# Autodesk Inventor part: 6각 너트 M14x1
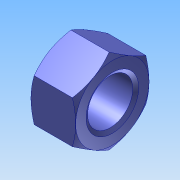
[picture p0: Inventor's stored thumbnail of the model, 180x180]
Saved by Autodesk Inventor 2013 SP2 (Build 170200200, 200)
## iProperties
Created: 2025-08
Part Number: 6각 너트 M14x1
Material: Generic
Document SubType Name: Modeling
Designer: i
Density: 1 g/cm^3
Author: i
변환 표준: STEP AP214IS
전처리기: Build: 200, Release: 2013 SP2 Update 6 - Date: Thu 07/17/2014
전송 단위: 밀리미터
불확실성: 0.01
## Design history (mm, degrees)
node "6각 너트 M14x11"
body "Solid1"
node "기준1"
